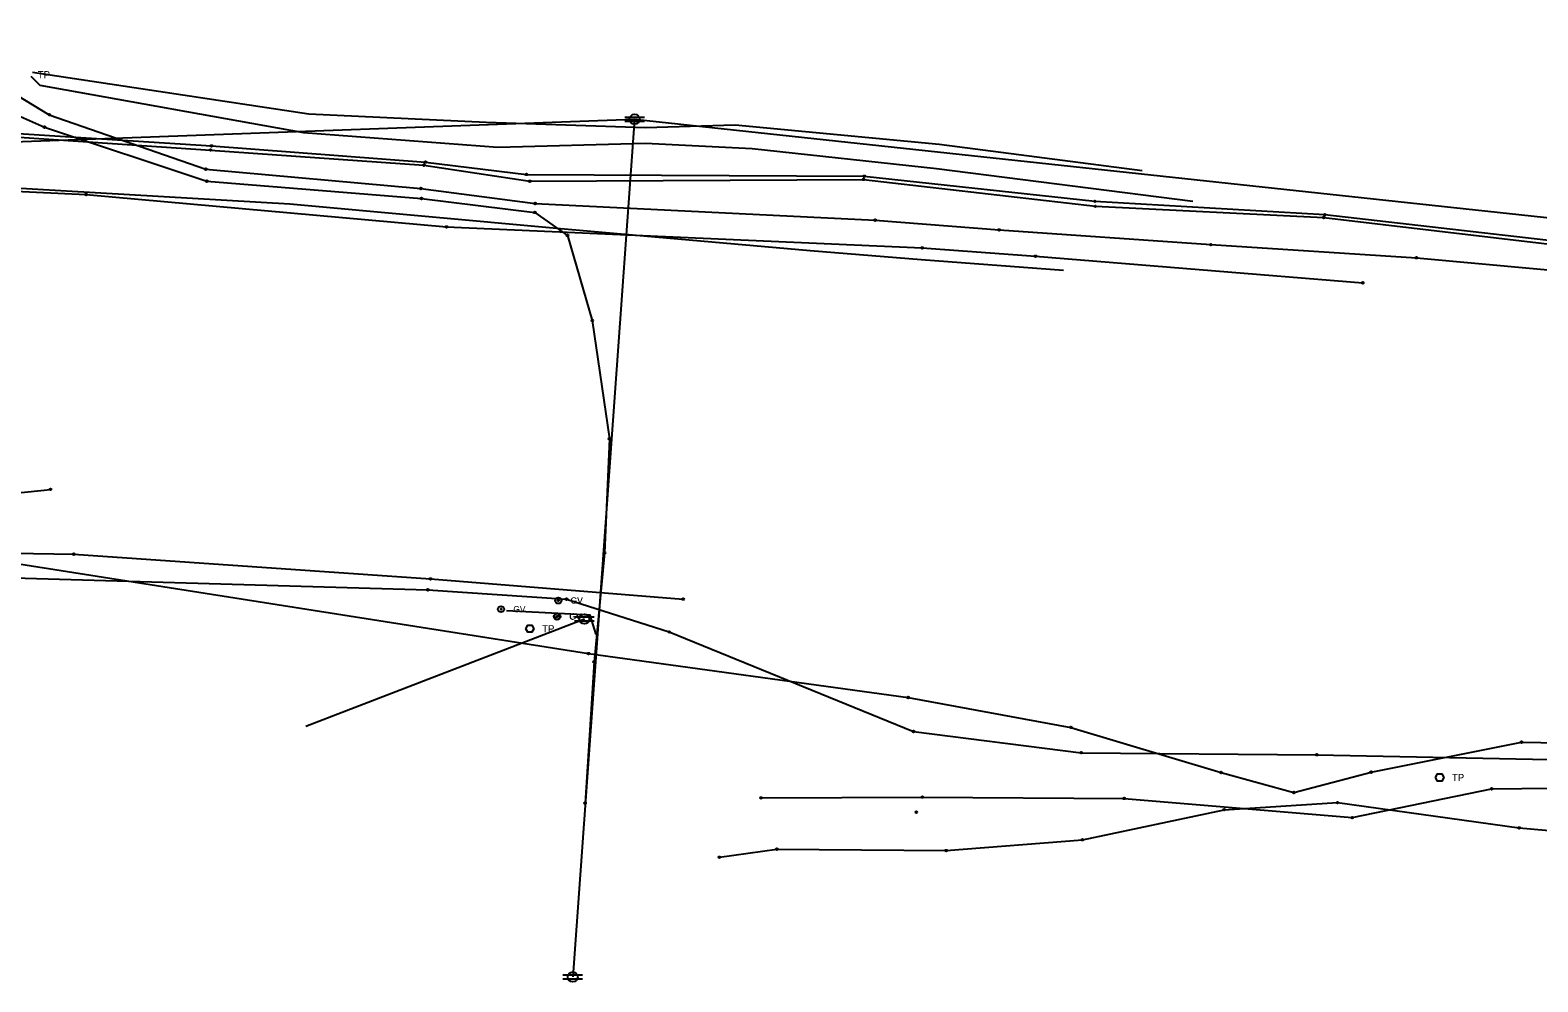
# Model space of a CAD drawing. Extents: x 20500343 to 20505311, y 7953484 to 7954193.
# Drawn here: x 20501326.9 to 20501663.2, y 7953801.6 to 7954013.9 of the extents above; entities that cross this region are included whole.
import ezdxf

# ---------------------------------------------------------------- set-up
doc = ezdxf.new("R2010")
doc.units = 0
for name, color, linetype in [('C-PROP-LINE-LOT', 7, 'Continuous'), ('V-ANNO-BNDY', 7, 'Continuous'), ('V-ANNO-NOTE', 7, 'Continuous'), ('V-CTRL-HVPT', 7, 'Continuous'), ('V-MON-FND', 7, 'Continuous'), ('V-SITE-FENC', 7, 'Continuous')]:
    doc.layers.add(name, color=color, linetype=linetype)

msp = doc.modelspace()

# ---------------------------------------------------------------- linework, layer by layer
at = {"layer": 'C-PROP-LINE-LOT'}
for points in [[(20500542.46, 7954013.94), (20500614.61, 7954008.93), (20500657.56, 7954005.52), (20500702.03, 7954001.63), (20500823.93, 7953990.08), (20500894.24, 7953984.51), (20500998.83, 7953975.83), (20501086.53, 7953973.45), (20501164.96, 7953976.11), (20501261.79, 7953980.89), (20501339.33, 7953977.27), (20501419.74, 7953970.03), (20501525.89, 7953965.34), (20501551.15, 7953963.49), (20501624.16, 7953957.55)], [(20501316.97, 7954003.56), (20501331.13, 7953995.08), (20501366.04, 7953982.93), (20501414.04, 7953978.62), (20501439.53, 7953975.27), (20501515.39, 7953971.55), (20501543.03, 7953969.36), (20501590.25, 7953966.08), (20501636.14, 7953963.16), (20501689.01, 7953958.28), (20501726.44, 7953956.52), (20501746.18, 7953958.43), (20501775.61, 7953959.04)], [(20501326.98, 7954003.64), (20501328.99, 7954001.63), (20501387.83, 7953991.08), (20501431.2, 7953987.84), (20501464.15, 7953988.7), (20501487.98, 7953987.54), (20501529.06, 7953983.1), (20501586.24, 7953975.78)], [(20501327.41, 7954004.55), (20501389.03, 7953995.3), (20501428.62, 7953993.39), (20501464.18, 7953992.24), (20501484.13, 7953992.79), (20501529.7, 7953988.52), (20501574.93, 7953982.61)], [(20501315.95, 7953998.55), (20501330.06, 7953992.29), (20501366.28, 7953980.24), (20501414.18, 7953976.37), (20501439.46, 7953973.28), (20501446.74, 7953968.11), (20501452.28, 7953949.16), (20501456.12, 7953922.73), (20501455.01, 7953897.31), (20501452.69, 7953873.02), (20501450.67, 7953841.46)], [(20500996.43, 7953915.71), (20500994.86, 7953939.31), (20500993.84, 7953971.13), (20500992.21, 7953991.99), (20500998.39, 7953997.86), (20501033.4, 7953996.49), (20501087.77, 7953993.38), (20501147.66, 7953991.76), (20501204.37, 7953990.78), (20501258.68, 7953993.69), (20501291.5, 7953992.96), (20501367.31, 7953988.1), (20501415.06, 7953984.51), (20501437.58, 7953981.75), (20501512.96, 7953981.34), (20501564.43, 7953975.75), (20501615.72, 7953972.77), (20501679.29, 7953965.51), (20501737.55, 7953960.19), (20501775.55, 7953956.71)], [(20500997.07, 7953915.68), (20500995.89, 7953938.94), (20500994.71, 7953971.1), (20500993, 7953991.18), (20500998.42, 7953997.06), (20501033.28, 7953995.67), (20501087.63, 7953992.68), (20501147.58, 7953990.88), (20501204.03, 7953989.96), (20501258.58, 7953992.74), (20501291.52, 7953992.27), (20501367.1, 7953987.19), (20501414.72, 7953983.8), (20501438.34, 7953980.22), (20501512.8, 7953980.63), (20501564.51, 7953974.63), (20501615.49, 7953972.13), (20501679.12, 7953964.62), (20501737.42, 7953959.32), (20501775.43, 7953955.89)], [(20501106.27, 7953988.97), (20501270.01, 7953987.09), (20501461.7, 7953994.07)], [(20501461.7, 7953994.07), (20501447.92, 7953802.7)], [(20501461.7, 7953994.07), (20501696.91, 7953968.73), (20501941.48, 7953944.15)], [(20501297.64, 7953979.33), (20501313.17, 7953979.32), (20501384.83, 7953975.15), (20501444.4, 7953969.74), (20501500.9, 7953964.74), (20501525.63, 7953962.76), (20501557.44, 7953960.37)], [(20500520.98, 7953977.28), (20500560.2, 7953972.18), (20500580.11, 7953968.09), (20500618.43, 7953964.47), (20500633.81, 7953963.45), (20500668.21, 7953960.34), (20500693.49, 7953957.8), (20500747.72, 7953955.96), (20500802.14, 7953953.65), (20500876.21, 7953950.48), (20500928.48, 7953945.92), (20500984.31, 7953941.41), (20501068.76, 7953929.07), (20501169.59, 7953917.28), (20501247.95, 7953910.8), (20501285.38, 7953908.94), (20501306.14, 7953908.1), (20501320.57, 7953910.34), (20501331.41, 7953911.48)], [(20501303.19, 7953964.19), (20501304.16, 7953950.59), (20501305.04, 7953916.44), (20501305.05, 7953897.56), (20501336.58, 7953897.02), (20501416.18, 7953891.49), (20501472.56, 7953887.01)], [(20500998.83, 7953913.68), (20501022.94, 7953911.59), (20501056.17, 7953908.34), (20501118.67, 7953904.16), (20501155.66, 7953902.37), (20501207.31, 7953899.83), (20501244.54, 7953898.43), (20501286.93, 7953897.81), (20501305.79, 7953896.3), (20501317.66, 7953895.88), (20501451.4, 7953874.84), (20501522.75, 7953865.03), (20501559.04, 7953858.38), (20501592.55, 7953848.31), (20501608.82, 7953843.84), (20501626.02, 7953848.37), (20501659.58, 7953855.08), (20501681.27, 7953854.69), (20501701.7, 7953853.44), (20501722.46, 7953851.13), (20501765.84, 7953847.22)], [(20501263.02, 7953904.3), (20501263.23, 7953899.59), (20501267.6, 7953894.11), (20501302.56, 7953892.31), (20501415.59, 7953889.07), (20501446.52, 7953886.98), (20501469.46, 7953879.66), (20501523.96, 7953857.45), (20501561.35, 7953852.73), (20501613.91, 7953852.27), (20501680.57, 7953850.9), (20501710.93, 7953846.81), (20501733.66, 7953845.08), (20501733.32, 7953834.72), (20501764.02, 7953830.92)], [(20501388.36, 7953858.67), (20501450.51, 7953882.57)], [(20501489.92, 7953842.63), (20501525.91, 7953842.83), (20501570.93, 7953842.53), (20501621.81, 7953838.23), (20501652.93, 7953844.67), (20501686.76, 7953845.05), (20501717.8, 7953841.16), (20501764.61, 7953834.86)], [(20501480.62, 7953829.39), (20501493.47, 7953831.21), (20501531.23, 7953830.89), (20501561.61, 7953833.31), (20501593.25, 7953840.01), (20501618.52, 7953841.58), (20501659.08, 7953835.94), (20501726.17, 7953830)]]:
    msp.add_lwpolyline(points, dxfattribs=at)
at = {"layer": 'V-ANNO-BNDY'}
msp.add_line((20501524.57, 7953839.45), (20501524.57, 7953839.45), dxfattribs=at)
msp.add_lwpolyline([(20501453.16, 7953879.09), (20501451.81, 7953883.39), (20501433.17, 7953884.38)], dxfattribs=at)
for centre, radius in [((20501444.68, 7953886.68), 0.685), ((20501444.73, 7953886.68), 0.685), ((20501431.92, 7953884.75), 0.685), ((20501431.92, 7953884.75), 0.114), ((20501444.37, 7953883.08), 0.685), ((20501444.49, 7953883.15), 0.685), ((20501444.68, 7953886.68), 0.114), ((20501444.73, 7953886.68), 0.114), ((20501444.37, 7953883.08), 0.114), ((20501444.49, 7953883.15), 0.114)]:
    msp.add_circle(centre, radius, dxfattribs=at)
at = {"layer": 'V-ANNO-NOTE'}
for centre in [(20501331.13, 7953995.08), (20501330.06, 7953992.29), (20501367.31, 7953988.1), (20501367.1, 7953987.19), (20501415.06, 7953984.51), (20501366.04, 7953982.93), (20501414.72, 7953983.8), (20501437.58, 7953981.75), (20501512.96, 7953981.34), (20501366.28, 7953980.24), (20501414.04, 7953978.62), (20501438.34, 7953980.22), (20501512.8, 7953980.63), (20501339.33, 7953977.27), (20501414.18, 7953976.37), (20501439.53, 7953975.27), (20501564.43, 7953975.75), (20501564.51, 7953974.63), (20501439.46, 7953973.28), (20501515.39, 7953971.55), (20501615.49, 7953972.13), (20501615.72, 7953972.77), (20501419.74, 7953970.03), (20501446.74, 7953968.11), (20501543.03, 7953969.36), (20501525.89, 7953965.34), (20501590.25, 7953966.08), (20501551.15, 7953963.49), (20501636.14, 7953963.16), (20501624.16, 7953957.55), (20501452.28, 7953949.16), (20501456.12, 7953922.73), (20501331.41, 7953911.48), (20501336.58, 7953897.02), (20501455.01, 7953897.31), (20501416.18, 7953891.49), (20501415.59, 7953889.07), (20501446.52, 7953886.98), (20501472.56, 7953887.01), (20501469.46, 7953879.66), (20501451.4, 7953874.84), (20501452.69, 7953873.02), (20501522.75, 7953865.03), (20501523.96, 7953857.45), (20501559.04, 7953858.38), (20501659.58, 7953855.08), (20501561.35, 7953852.73), (20501613.91, 7953852.27), (20501592.55, 7953848.31), (20501626.02, 7953848.37), (20501608.82, 7953843.84), (20501652.93, 7953844.67), (20501450.67, 7953841.46), (20501489.92, 7953842.63), (20501525.91, 7953842.83), (20501570.93, 7953842.53), (20501593.25, 7953840.01), (20501618.52, 7953841.58), (20501524.57, 7953839.45), (20501621.81, 7953838.23), (20501561.61, 7953833.31), (20501659.08, 7953835.94), (20501493.47, 7953831.21), (20501531.23, 7953830.89), (20501480.62, 7953829.39)]:
    msp.add_circle(centre, 0.2, dxfattribs=at)
at = {"layer": 'V-CTRL-HVPT'}
for p, q in [((20501459.5, 7953994.51), (20501463.9, 7953994.51)), ((20501459.5, 7953993.63), (20501463.9, 7953993.63)), ((20501448.31, 7953883.01), (20501452.71, 7953883.01)), ((20501448.31, 7953882.13), (20501452.71, 7953882.13)), ((20501445.72, 7953803.14), (20501450.12, 7953803.14)), ((20501445.72, 7953802.26), (20501450.12, 7953802.26))]:
    msp.add_line(p, q, dxfattribs=at)
for centre in [(20501461.7, 7953994.07), (20501450.51, 7953882.57), (20501447.92, 7953802.7)]:
    msp.add_circle(centre, 1.1, dxfattribs=at)
at = {"layer": 'V-MON-FND'}
msp.add_lwpolyline([(20501437.44, 7953880.38), (20501437.89, 7953881.17), (20501438.81, 7953881.17), (20501439.26, 7953880.38), (20501438.81, 7953879.59), (20501437.89, 7953879.59), (20501437.44, 7953880.38)], dxfattribs=at)
at = {"layer": 'V-SITE-FENC'}
msp.add_lwpolyline([(20501640.43, 7953847.19), (20501640.88, 7953847.98), (20501641.8, 7953847.98), (20501642.25, 7953847.19), (20501641.8, 7953846.4), (20501640.88, 7953846.4), (20501640.43, 7953847.19)], dxfattribs=at)

# ---------------------------------------------------------------- texts
at = {"layer": 'V-ANNO-BNDY'}
for p in [(20501447.42, 7953885.98), (20501447.47, 7953885.98), (20501434.66, 7953884.05), (20501447.11, 7953882.38), (20501447.23, 7953882.45)]:
    msp.add_text('GV', height=1.399, dxfattribs=at).set_placement(p)
at = {"layer": 'V-MON-FND'}
for p in [(20501328.56, 7954003.19), (20501441.09, 7953879.58)]:
    msp.add_text('TP', height=1.599, dxfattribs=at).set_placement(p)
at = {"layer": 'V-SITE-FENC'}
msp.add_text('TP', height=1.599, dxfattribs=at).set_placement((20501644.08, 7953846.39))

doc.saveas('drawing.dxf')
